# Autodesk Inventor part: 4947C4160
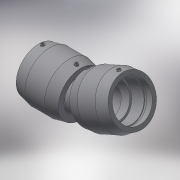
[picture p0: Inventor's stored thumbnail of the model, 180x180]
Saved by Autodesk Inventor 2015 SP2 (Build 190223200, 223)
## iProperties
Created: 2017-06
Part Number: 4947C4160
Material: Generic
Description: PLASSON ADJUSTABLE ELBOW 160
Document SubType Name: Modeling
Designer: KIM
Mass: 6381.31 g
Surface Area: 5796.39 cm^2
Volume: 6381.31 cm^3
Density: 1 g/cm^3
Appearance: Default
Author: KIM
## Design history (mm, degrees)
derived "4947C4.ipt"
feature "Solid1::4947C4.ipt"
tag "TaggingFeature1"
body "Solid1"
other parameters: "d0" = 181.2, "d2" = 215, "d3" = 97, "d4" = 48.5, "d5" = 193.5, "d8" = 168 deg, "d10" = 38.8, "d11" = 12.93333, "d29" = 106, "d30" = 15, "d31" = 72.48, "d34" = 5 deg, "d41" = 4, "d42" = 14, "d43" = 0, "d48" = 144, "d49" = 24 deg, "d50" = 453, "d51" = 78 deg, "d52" = 90 deg, "d55" = 42.1, "d57" = 168 deg, "d58" = 8.42, "d60" = 51.17631, "d62" = 3, "d63" = 0, "L_" = 453, "L_1" = 97, "D_" = 215, "A_" = 106, "d_2" = 12, "L_0" = 148, "d54" = 84.2, "d59" = 170.58771
